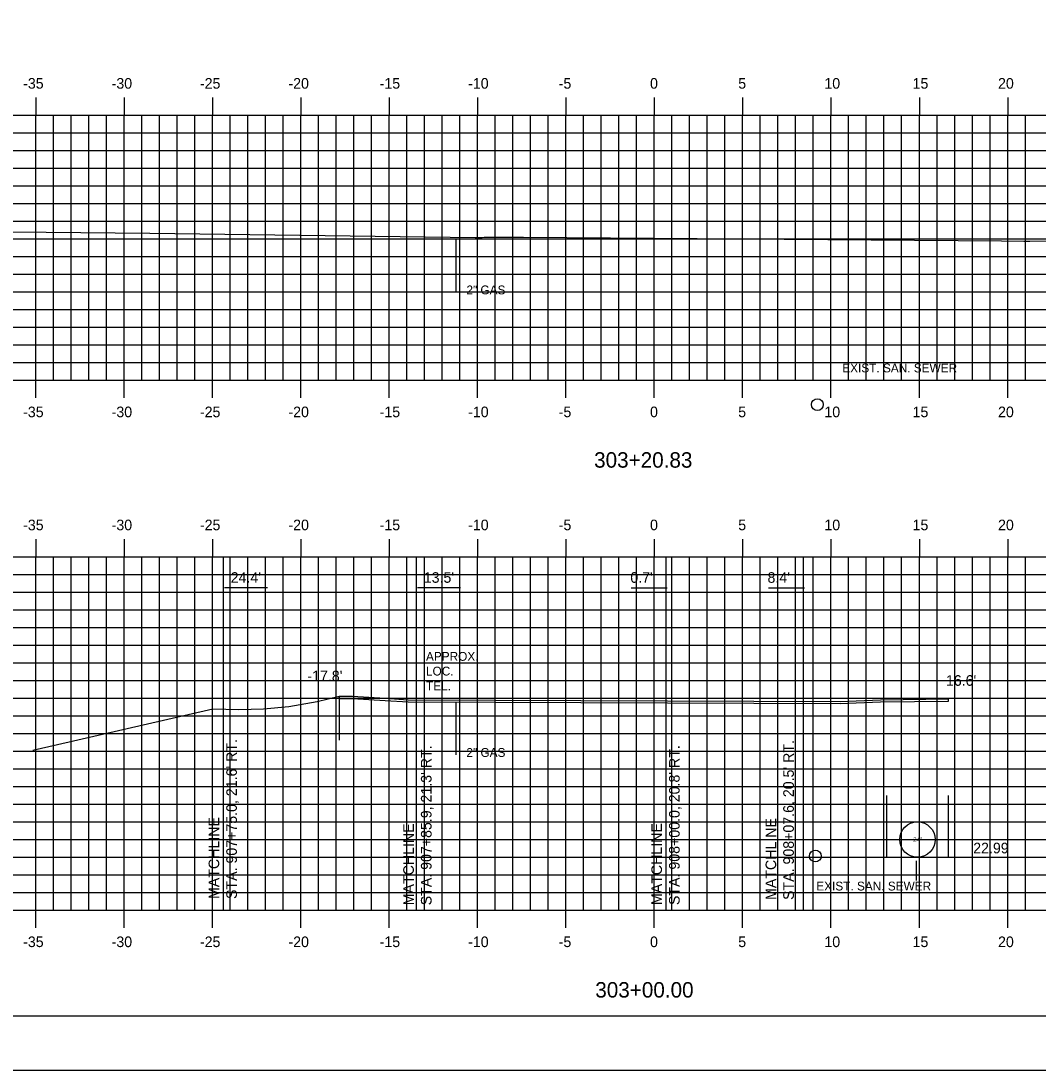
# Model space of a CAD drawing. Extents: x 1024350 to 1024520, y 394697 to 394807.
# Drawn here: x 1024397.2 to 1024454.7, y 394696.5 to 394755.9 of the extents above; entities that cross this region are included whole.
import ezdxf

# ---------------------------------------------------------------- set-up
doc = ezdxf.new("R2010")
doc.units = 0
for name, color, linetype in [('ANNOTATION', 7, 'Continuous'), ('BORDER', 7, 'Continuous'), ('D_Drainage_Text', 7, 'Continuous'), ('D_Drainage_Underdrain', 7, 'Continuous'), ('D_Roadway_FinishedGrade', 7, 'Continuous'), ('D_Text_Monospaced', 7, 'Continuous'), ('D_Text_Standard', 7, 'Continuous'), ('H_V ANNOTATION', 7, 'Continuous'), ('MAJOR', 7, 'Continuous'), ('MINOR', 7, 'Continuous'), ('PLOT BOUNDARY', 7, 'Continuous'), ('S_Roadway_Centerline', 7, 'Continuous'), ('S_Roadway_Edge_Pavement', 7, 'Continuous'), ('S_Utilities_UG_Gas_Line', 7, 'Continuous'), ('S_Utilities_UG_Sanitary_Sewer', 7, 'Continuous'), ('S_Utilities_UG_Telephone', 7, 'Continuous')]:
    doc.layers.add(name, color=color, linetype=linetype)

msp = doc.modelspace()

# ---------------------------------------------------------------- linework, layer by layer
at = {"layer": 'ANNOTATION'}
for p, q in [((1024411.111, 394723.85), (1024408.675, 394723.85)), ((1024422.038, 394723.85), (1024419.602, 394723.85)), ((1024431.697, 394723.85), (1024433.728, 394723.85)), ((1024439.463, 394723.85), (1024441.494, 394723.85)), ((1024415.173, 394717.589), (1024415.173, 394717.714))]:
    msp.add_line(p, q, dxfattribs=at)
msp.add_lwpolyline([(1024447.823, 394708.394), (1024447.823, 394708.289), (1024447.823, 394707.273)], dxfattribs=at)
at = {"layer": 'BORDER'}
msp.add_line((1024358.002, 394699.607), (1024518.002, 394699.607), dxfattribs=at)
at = {"layer": 'D_Drainage_Text'}
msp.add_line((1024450.296, 394708.597), (1024454.435, 394708.597), dxfattribs=at)
at = {"layer": 'D_Drainage_Underdrain'}
msp.add_lwpolyline([(1024446.146, 394712.098), (1024446.146, 394708.597), (1024449.646, 394708.597), (1024449.646, 394712.098)], dxfattribs=at)
msp.add_circle((1024447.896, 394709.597), 1, dxfattribs=at)
at = {"layer": 'D_Roadway_FinishedGrade'}
for p, q in [((1024408.621, 394705.607), (1024408.621, 394725.607)), ((1024419.549, 394705.607), (1024419.549, 394725.607)), ((1024433.675, 394705.607), (1024433.675, 394725.607)), ((1024441.441, 394705.607), (1024441.441, 394725.607)), ((1024449.646, 394717.431), (1024449.646, 394717.556))]:
    msp.add_line(p, q, dxfattribs=at)
for points in [[(1024415.173, 394717.714), (1024415.918, 394717.712), (1024417.772, 394717.598), (1024419.07, 394717.513), (1024443.527, 394717.418), (1024445.808, 394717.51), (1024449.646, 394717.556)], [(1024415.173, 394717.589), (1024415.918, 394717.587), (1024417.772, 394717.473), (1024419.07, 394717.388), (1024443.527, 394717.293), (1024445.808, 394717.385), (1024449.646, 394717.431)]]:
    msp.add_lwpolyline(points, dxfattribs=at)
at = {"layer": 'MAJOR'}
for p, q in [((1024398.002, 394751.609), (1024398.002, 394750.607)), ((1024403.002, 394751.609), (1024403.002, 394750.607)), ((1024408.002, 394751.609), (1024408.002, 394750.607)), ((1024413.002, 394751.609), (1024413.002, 394750.607)), ((1024418.002, 394751.609), (1024418.002, 394750.607)), ((1024423.002, 394751.609), (1024423.002, 394750.607)), ((1024428.002, 394751.609), (1024428.002, 394750.607)), ((1024433.002, 394751.609), (1024433.002, 394750.607)), ((1024438.002, 394751.609), (1024438.002, 394750.607)), ((1024443.002, 394751.609), (1024443.002, 394750.607)), ((1024448.002, 394751.609), (1024448.002, 394750.607)), ((1024453.002, 394751.609), (1024453.002, 394750.607)), ((1024363.002, 394750.607), (1024503.002, 394750.607)), ((1024398.002, 394735.607), (1024398.002, 394750.607)), ((1024403.002, 394735.607), (1024403.002, 394750.607)), ((1024408.002, 394735.607), (1024408.002, 394750.607)), ((1024413.002, 394735.607), (1024413.002, 394750.607)), ((1024418.002, 394735.607), (1024418.002, 394750.607)), ((1024423.002, 394735.607), (1024423.002, 394750.607)), ((1024428.002, 394735.607), (1024428.002, 394750.607)), ((1024433.002, 394735.607), (1024433.002, 394750.607)), ((1024438.002, 394735.607), (1024438.002, 394750.607)), ((1024443.002, 394735.607), (1024443.002, 394750.607)), ((1024448.002, 394735.607), (1024448.002, 394750.607)), ((1024453.002, 394735.607), (1024453.002, 394750.607)), ((1024363.002, 394745.607), (1024503.002, 394745.607)), ((1024363.002, 394740.607), (1024503.002, 394740.607)), ((1024363.002, 394735.607), (1024503.002, 394735.607)), ((1024398.002, 394734.605), (1024398.002, 394735.607)), ((1024403.002, 394734.605), (1024403.002, 394735.607)), ((1024408.002, 394734.605), (1024408.002, 394735.607)), ((1024413.002, 394734.605), (1024413.002, 394735.607)), ((1024418.002, 394734.605), (1024418.002, 394735.607)), ((1024423.002, 394734.605), (1024423.002, 394735.607)), ((1024428.002, 394734.605), (1024428.002, 394735.607)), ((1024433.002, 394734.605), (1024433.002, 394735.607)), ((1024438.002, 394734.605), (1024438.002, 394735.607)), ((1024443.002, 394734.605), (1024443.002, 394735.607)), ((1024448.002, 394734.605), (1024448.002, 394735.607)), ((1024453.002, 394734.605), (1024453.002, 394735.607)), ((1024398.002, 394726.609), (1024398.002, 394725.607)), ((1024403.002, 394726.609), (1024403.002, 394725.607)), ((1024408.002, 394726.609), (1024408.002, 394725.607)), ((1024413.002, 394726.609), (1024413.002, 394725.607)), ((1024418.002, 394726.609), (1024418.002, 394725.607)), ((1024423.002, 394726.609), (1024423.002, 394725.607)), ((1024428.002, 394726.609), (1024428.002, 394725.607)), ((1024433.002, 394726.609), (1024433.002, 394725.607)), ((1024438.002, 394726.609), (1024438.002, 394725.607)), ((1024443.002, 394726.609), (1024443.002, 394725.607)), ((1024448.002, 394726.609), (1024448.002, 394725.607)), ((1024453.002, 394726.609), (1024453.002, 394725.607)), ((1024363.002, 394725.607), (1024503.002, 394725.607)), ((1024398.002, 394705.607), (1024398.002, 394725.607)), ((1024403.002, 394705.607), (1024403.002, 394725.607)), ((1024408.002, 394705.607), (1024408.002, 394725.607)), ((1024413.002, 394705.607), (1024413.002, 394725.607)), ((1024418.002, 394705.607), (1024418.002, 394725.607)), ((1024423.002, 394705.607), (1024423.002, 394725.607)), ((1024428.002, 394705.607), (1024428.002, 394725.607)), ((1024433.002, 394705.607), (1024433.002, 394725.607)), ((1024438.002, 394705.607), (1024438.002, 394725.607)), ((1024443.002, 394705.607), (1024443.002, 394725.607)), ((1024448.002, 394705.607), (1024448.002, 394725.607)), ((1024453.002, 394705.607), (1024453.002, 394725.607)), ((1024363.002, 394720.607), (1024503.002, 394720.607)), ((1024363.002, 394715.607), (1024503.002, 394715.607)), ((1024363.002, 394710.607), (1024503.002, 394710.607)), ((1024363.002, 394705.607), (1024503.002, 394705.607)), ((1024398.002, 394704.605), (1024398.002, 394705.607)), ((1024403.002, 394704.605), (1024403.002, 394705.607)), ((1024408.002, 394704.605), (1024408.002, 394705.607)), ((1024413.002, 394704.605), (1024413.002, 394705.607)), ((1024418.002, 394704.605), (1024418.002, 394705.607)), ((1024423.002, 394704.605), (1024423.002, 394705.607)), ((1024428.002, 394704.605), (1024428.002, 394705.607)), ((1024433.002, 394704.605), (1024433.002, 394705.607)), ((1024438.002, 394704.605), (1024438.002, 394705.607)), ((1024443.002, 394704.605), (1024443.002, 394705.607)), ((1024448.002, 394704.605), (1024448.002, 394705.607)), ((1024453.002, 394704.605), (1024453.002, 394705.607))]:
    msp.add_line(p, q, dxfattribs=at)
at = {"layer": 'MINOR'}
for p, q in [((1024399.002, 394735.607), (1024399.002, 394750.607)), ((1024400.002, 394735.607), (1024400.002, 394750.607)), ((1024401.002, 394735.607), (1024401.002, 394750.607)), ((1024402.002, 394735.607), (1024402.002, 394750.607)), ((1024404.002, 394735.607), (1024404.002, 394750.607)), ((1024405.002, 394735.607), (1024405.002, 394750.607)), ((1024406.002, 394735.607), (1024406.002, 394750.607)), ((1024407.002, 394735.607), (1024407.002, 394750.607)), ((1024409.002, 394735.607), (1024409.002, 394750.607)), ((1024410.002, 394735.607), (1024410.002, 394750.607)), ((1024411.002, 394735.607), (1024411.002, 394750.607)), ((1024412.002, 394735.607), (1024412.002, 394750.607)), ((1024414.002, 394735.607), (1024414.002, 394750.607)), ((1024415.002, 394735.607), (1024415.002, 394750.607)), ((1024416.002, 394735.607), (1024416.002, 394750.607)), ((1024417.002, 394735.607), (1024417.002, 394750.607)), ((1024419.002, 394735.607), (1024419.002, 394750.607)), ((1024420.002, 394735.607), (1024420.002, 394750.607)), ((1024421.002, 394735.607), (1024421.002, 394750.607)), ((1024422.002, 394735.607), (1024422.002, 394750.607)), ((1024424.002, 394735.607), (1024424.002, 394750.607)), ((1024425.002, 394735.607), (1024425.002, 394750.607)), ((1024426.002, 394735.607), (1024426.002, 394750.607)), ((1024427.002, 394735.607), (1024427.002, 394750.607)), ((1024429.002, 394735.607), (1024429.002, 394750.607)), ((1024430.002, 394735.607), (1024430.002, 394750.607)), ((1024431.002, 394735.607), (1024431.002, 394750.607)), ((1024432.002, 394735.607), (1024432.002, 394750.607)), ((1024434.002, 394735.607), (1024434.002, 394750.607)), ((1024435.002, 394735.607), (1024435.002, 394750.607)), ((1024436.002, 394735.607), (1024436.002, 394750.607)), ((1024437.002, 394735.607), (1024437.002, 394750.607)), ((1024439.002, 394735.607), (1024439.002, 394750.607)), ((1024440.002, 394735.607), (1024440.002, 394750.607)), ((1024441.002, 394735.607), (1024441.002, 394750.607)), ((1024442.002, 394735.607), (1024442.002, 394750.607)), ((1024444.002, 394735.607), (1024444.002, 394750.607)), ((1024445.002, 394735.607), (1024445.002, 394750.607)), ((1024446.002, 394735.607), (1024446.002, 394750.607)), ((1024447.002, 394735.607), (1024447.002, 394750.607)), ((1024449.002, 394735.607), (1024449.002, 394750.607)), ((1024450.002, 394735.607), (1024450.002, 394750.607)), ((1024451.002, 394735.607), (1024451.002, 394750.607)), ((1024452.002, 394735.607), (1024452.002, 394750.607)), ((1024454.002, 394735.607), (1024454.002, 394750.607)), ((1024363.002, 394749.607), (1024503.002, 394749.607)), ((1024363.002, 394748.607), (1024503.002, 394748.607)), ((1024363.002, 394747.607), (1024503.002, 394747.607)), ((1024363.002, 394746.607), (1024503.002, 394746.607)), ((1024363.002, 394744.607), (1024503.002, 394744.607)), ((1024363.002, 394743.607), (1024503.002, 394743.607)), ((1024363.002, 394742.607), (1024503.002, 394742.607)), ((1024363.002, 394741.607), (1024503.002, 394741.607)), ((1024363.002, 394739.607), (1024503.002, 394739.607)), ((1024363.002, 394738.607), (1024503.002, 394738.607)), ((1024363.002, 394737.607), (1024503.002, 394737.607)), ((1024363.002, 394736.607), (1024503.002, 394736.607)), ((1024399.002, 394705.607), (1024399.002, 394725.607)), ((1024400.002, 394705.607), (1024400.002, 394725.607)), ((1024401.002, 394705.607), (1024401.002, 394725.607)), ((1024402.002, 394705.607), (1024402.002, 394725.607)), ((1024404.002, 394705.607), (1024404.002, 394725.607)), ((1024405.002, 394705.607), (1024405.002, 394725.607)), ((1024406.002, 394705.607), (1024406.002, 394725.607)), ((1024407.002, 394705.607), (1024407.002, 394725.607)), ((1024409.002, 394705.607), (1024409.002, 394725.607)), ((1024410.002, 394705.607), (1024410.002, 394725.607)), ((1024411.002, 394705.607), (1024411.002, 394725.607)), ((1024412.002, 394705.607), (1024412.002, 394725.607)), ((1024414.002, 394705.607), (1024414.002, 394725.607)), ((1024415.002, 394705.607), (1024415.002, 394725.607)), ((1024416.002, 394705.607), (1024416.002, 394725.607)), ((1024417.002, 394705.607), (1024417.002, 394725.607)), ((1024419.002, 394705.607), (1024419.002, 394725.607)), ((1024420.002, 394705.607), (1024420.002, 394725.607)), ((1024421.002, 394705.607), (1024421.002, 394725.607)), ((1024422.002, 394705.607), (1024422.002, 394725.607)), ((1024424.002, 394705.607), (1024424.002, 394725.607)), ((1024425.002, 394705.607), (1024425.002, 394725.607)), ((1024426.002, 394705.607), (1024426.002, 394725.607)), ((1024427.002, 394705.607), (1024427.002, 394725.607)), ((1024429.002, 394705.607), (1024429.002, 394725.607)), ((1024430.002, 394705.607), (1024430.002, 394725.607)), ((1024431.002, 394705.607), (1024431.002, 394725.607)), ((1024432.002, 394705.607), (1024432.002, 394725.607)), ((1024434.002, 394705.607), (1024434.002, 394725.607)), ((1024435.002, 394705.607), (1024435.002, 394725.607)), ((1024436.002, 394705.607), (1024436.002, 394725.607)), ((1024437.002, 394705.607), (1024437.002, 394725.607)), ((1024439.002, 394705.607), (1024439.002, 394725.607)), ((1024440.002, 394705.607), (1024440.002, 394725.607)), ((1024441.002, 394705.607), (1024441.002, 394725.607)), ((1024442.002, 394705.607), (1024442.002, 394725.607)), ((1024444.002, 394705.607), (1024444.002, 394725.607)), ((1024445.002, 394705.607), (1024445.002, 394725.607)), ((1024446.002, 394705.607), (1024446.002, 394725.607)), ((1024447.002, 394705.607), (1024447.002, 394725.607)), ((1024449.002, 394705.607), (1024449.002, 394725.607)), ((1024450.002, 394705.607), (1024450.002, 394725.607)), ((1024451.002, 394705.607), (1024451.002, 394725.607)), ((1024452.002, 394705.607), (1024452.002, 394725.607)), ((1024454.002, 394705.607), (1024454.002, 394725.607)), ((1024363.002, 394724.607), (1024503.002, 394724.607)), ((1024363.002, 394723.607), (1024503.002, 394723.607)), ((1024363.002, 394722.607), (1024503.002, 394722.607)), ((1024363.002, 394721.607), (1024503.002, 394721.607)), ((1024363.002, 394719.607), (1024503.002, 394719.607)), ((1024363.002, 394718.607), (1024503.002, 394718.607)), ((1024363.002, 394717.607), (1024503.002, 394717.607)), ((1024363.002, 394716.607), (1024503.002, 394716.607)), ((1024363.002, 394714.607), (1024503.002, 394714.607)), ((1024363.002, 394713.607), (1024503.002, 394713.607)), ((1024363.002, 394712.607), (1024503.002, 394712.607)), ((1024363.002, 394711.607), (1024503.002, 394711.607)), ((1024363.002, 394709.607), (1024503.002, 394709.607)), ((1024363.002, 394708.607), (1024503.002, 394708.607)), ((1024363.002, 394707.607), (1024503.002, 394707.607)), ((1024363.002, 394706.607), (1024503.002, 394706.607))]:
    msp.add_line(p, q, dxfattribs=at)
at = {"layer": 'PLOT BOUNDARY'}
msp.add_lwpolyline([(1024349.909, 394696.548), (1024519.909, 394696.548), (1024519.909, 394806.548), (1024349.909, 394806.548)], close=True, dxfattribs=at)
at = {"layer": 'S_Roadway_Centerline'}
for points in [[(1024363.002, 394744.661), (1024389.193, 394744.097), (1024390.079, 394744.083), (1024390.738, 394744.068), (1024404.458, 394743.926), (1024422.871, 394743.689), (1024423.133, 394743.69), (1024423.252, 394743.69), (1024423.368, 394743.693), (1024423.473, 394743.695), (1024423.535, 394743.696), (1024425.607, 394743.694), (1024452.655, 394743.489), (1024453.91, 394743.47), (1024454.075, 394743.469), (1024454.263, 394743.469), (1024459.693, 394743.513)], [(1024397.827, 394714.654), (1024408.013, 394716.994), (1024409.485, 394716.954), (1024410.886, 394716.997), (1024412.318, 394717.134), (1024413.913, 394717.404), (1024415.173, 394717.714), (1024415.918, 394717.712), (1024417.772, 394717.598), (1024419.07, 394717.513), (1024443.527, 394717.418), (1024445.808, 394717.51), (1024449.646, 394717.556)]]:
    msp.add_lwpolyline(points, dxfattribs=at)
at = {"layer": 'S_Roadway_Edge_Pavement'}
msp.add_line((1024415.173, 394717.714), (1024415.173, 394715.214), dxfattribs=at)
at = {"layer": 'S_Utilities_UG_Gas_Line'}
for p, q in [((1024421.766, 394743.59), (1024421.766, 394740.59)), ((1024421.766, 394717.401), (1024421.766, 394714.401))]:
    msp.add_line(p, q, dxfattribs=at)
at = {"layer": 'S_Utilities_UG_Sanitary_Sewer'}
for centre in [(1024442.234, 394734.22), (1024442.117, 394708.66)]:
    msp.add_circle(centre, 0.333, dxfattribs=at)
at = {"layer": 'S_Utilities_UG_Telephone'}
msp.add_line((1024421.002, 394714.506), (1024421.002, 394717.506), dxfattribs=at)

# ---------------------------------------------------------------- texts
at = {"layer": 'ANNOTATION'}
for s, p in [("24.4'", (1024409.028, 394724.132)), ("13.5'", (1024419.956, 394724.132)), ("0.7'", (1024431.646, 394724.132)), ("8.4'", (1024439.411, 394724.132))]:
    msp.add_text(s, height=0.6, dxfattribs=at).set_placement(p)
for s, p in [("STA. 907+75.0, 21.6' RT.", (1024409.379, 394706.231)), ("STA. 908+07.6, 20.5' RT.", (1024440.9, 394706.176)), ("STA. 907+85.9, 21.3' RT.", (1024420.395, 394705.873)), ("STA. 908+00.0, 20.8' RT.", (1024434.436, 394705.887)), ('MATCHLINE', (1024408.379, 394706.231)), ('MATCHLINE', (1024439.9, 394706.176)), ('MATCHLINE', (1024419.395, 394705.873)), ('MATCHLINE', (1024433.436, 394705.887))]:
    msp.add_text(s, height=0.6, rotation=90, dxfattribs=at).set_placement(p)
at = {"layer": 'D_Drainage_Text'}
msp.add_text('22.99', height=0.6, dxfattribs=at).set_placement((1024451.05, 394708.814))
at = {"layer": 'D_Drainage_Underdrain'}
msp.add_text('24"', height=0.25, dxfattribs=at).set_placement((1024447.654, 394709.472))
at = {"layer": 'D_Text_Monospaced'}
for s, height, p in [('2" GAS', 0.5, (1024422.37, 394740.463)), ('EXIST. SAN. SEWER', 0.49998, (1024443.64, 394736.045)), ('APPROX.', 0.5, (1024420.081, 394719.716)), ('LOC.', 0.5, (1024420.081, 394718.883)), ('TEL.', 0.5, (1024420.081, 394718.05)), ('2" GAS', 0.5, (1024422.37, 394714.274)), ('EXIST. SAN. SEWER', 0.49998, (1024442.17, 394706.712))]:
    msp.add_text(s, height=height, dxfattribs=at).set_placement(p)
at = {"layer": 'D_Text_Standard'}
for s, p in [("-17.8'", (1024413.369, 394718.557)), ("16.6'", (1024449.508, 394718.301))]:
    msp.add_text(s, height=0.6, dxfattribs=at).set_placement(p)
at = {"layer": 'H_V ANNOTATION'}
for s, height, p in [('-35', 0.6, (1024397.282, 394752.107)), ('-30', 0.6, (1024402.29, 394752.107)), ('-25', 0.6, (1024407.288, 394752.107)), ('-20', 0.6, (1024412.296, 394752.107)), ('-15', 0.6, (1024417.459, 394752.107)), ('-10', 0.6, (1024422.467, 394752.107)), ('-5', 0.6, (1024427.593, 394752.107)), ('0', 0.6, (1024432.761, 394752.107)), ('5', 0.6, (1024437.753, 394752.107)), ('10', 0.6, (1024442.628, 394752.107)), ('15', 0.6, (1024447.62, 394752.107)), ('20', 0.6, (1024452.456, 394752.107)), ('-35', 0.6, (1024397.282, 394733.507)), ('-30', 0.6, (1024402.29, 394733.507)), ('-25', 0.6, (1024407.288, 394733.507)), ('-20', 0.6, (1024412.296, 394733.507)), ('-15', 0.6, (1024417.459, 394733.507)), ('-10', 0.6, (1024422.467, 394733.507)), ('-5', 0.6, (1024427.593, 394733.507)), ('0', 0.6, (1024432.761, 394733.507)), ('5', 0.6, (1024437.753, 394733.507)), ('10', 0.6, (1024442.628, 394733.507)), ('15', 0.6, (1024447.62, 394733.507)), ('20', 0.6, (1024452.456, 394733.507)), ('303+20.83', 0.875, (1024429.596, 394730.65)), ('-35', 0.6, (1024397.282, 394727.107)), ('-30', 0.6, (1024402.29, 394727.107)), ('-25', 0.6, (1024407.288, 394727.107)), ('-20', 0.6, (1024412.296, 394727.107)), ('-15', 0.6, (1024417.459, 394727.107)), ('-10', 0.6, (1024422.467, 394727.107)), ('-5', 0.6, (1024427.593, 394727.107)), ('0', 0.6, (1024432.761, 394727.107)), ('5', 0.6, (1024437.753, 394727.107)), ('10', 0.6, (1024442.628, 394727.107)), ('15', 0.6, (1024447.62, 394727.107)), ('20', 0.6, (1024452.456, 394727.107)), ('-35', 0.6, (1024397.282, 394703.507)), ('-30', 0.6, (1024402.29, 394703.507)), ('-25', 0.6, (1024407.288, 394703.507)), ('-20', 0.6, (1024412.296, 394703.507)), ('-15', 0.6, (1024417.459, 394703.507)), ('-10', 0.6, (1024422.467, 394703.507)), ('-5', 0.6, (1024427.593, 394703.507)), ('0', 0.6, (1024432.761, 394703.507)), ('5', 0.6, (1024437.753, 394703.507)), ('10', 0.6, (1024442.628, 394703.507)), ('15', 0.6, (1024447.62, 394703.507)), ('20', 0.6, (1024452.456, 394703.507)), ('303+00.00', 0.875, (1024429.662, 394700.65))]:
    msp.add_text(s, height=height, dxfattribs=at).set_placement(p)
at = {"layer": 'S_Roadway_Centerline'}
for s, p in [('C', (1024404.453, 394743.926)), ('L', (1024404.458, 394743.919))]:
    msp.add_text(s, height=0.0146, dxfattribs=at).set_placement(p)

doc.saveas('drawing.dxf')
